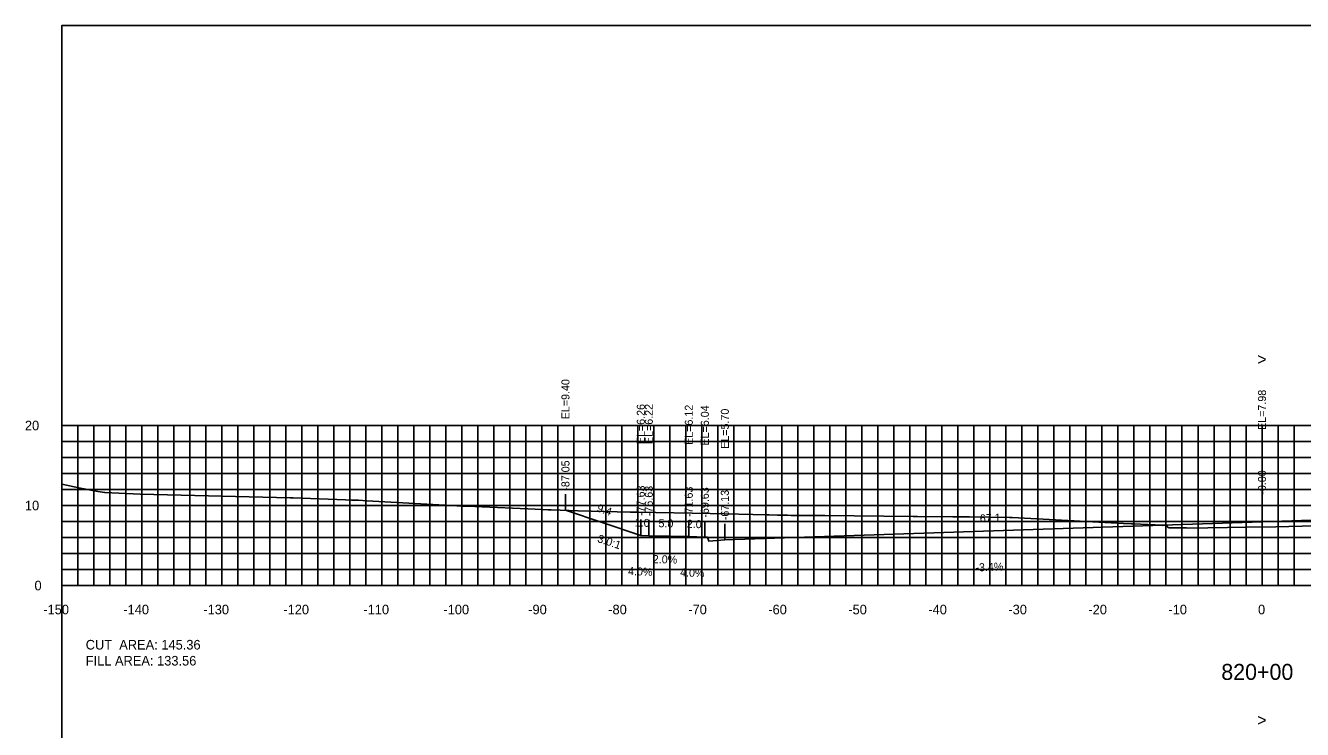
# Model space of a CAD drawing. Extents: x 1797419 to 1809236, y 248759 to 251512.
# Drawn here: x 1805876.5 to 1806036.1, y 250956.9 to 251044.9 of the extents above; entities that cross this region are included whole.
import ezdxf

# ---------------------------------------------------------------- set-up
doc = ezdxf.new("R2010")
doc.units = 0
for name, color, linetype in [('1', 7, 'Continuous'), ('10', 7, 'Continuous'), ('3', 7, 'Continuous'), ('31', 7, 'Continuous'), ('4', 7, 'Continuous'), ('60', 7, 'Continuous'), ('ANNO-TXT', 7, 'Continuous'), ('CL-CNST', 7, 'Continuous'), ('Level 62', 7, 'Continuous'), ('M-ROADS', 7, 'Continuous')]:
    doc.layers.add(name, color=color, linetype=linetype)

msp = doc.modelspace()

# ---------------------------------------------------------------- linework, layer by layer
for p, q in [((1805943.95, 250984.29), (1805943.95, 250986.29)), ((1806031, 250982.87), (1806031, 250984.87)), ((1805953.37, 250981.15), (1805953.37, 250983.15)), ((1805954.37, 250981.11), (1805954.37, 250983.11)), ((1805959.37, 250981.01), (1805959.37, 250983.01)), ((1805961.37, 250980.93), (1805961.37, 250982.93)), ((1805963.87, 250980.59), (1805963.87, 250982.59))]:
    msp.add_line(p, q)
msp.add_lwpolyline([(1805881, 250854.89), (1806181, 250854.89), (1806181, 251044.89), (1805881, 251044.89)], close=True)
at = {"layer": '60'}
for p, q in [((1805880.94, 250994.89), (1805881, 250994.89)), ((1805881, 250974.89), (1805881, 250994.89)), ((1805880.94, 250984.89), (1805881, 250984.89)), ((1805880.94, 250974.89), (1805881, 250974.89)), ((1805881, 250974.89), (1806181, 250974.89)), ((1805881, 250974.83), (1805881, 250974.89)), ((1805891, 250974.83), (1805891, 250974.89)), ((1805901, 250974.83), (1805901, 250974.89)), ((1805911, 250974.83), (1805911, 250974.89)), ((1805921, 250974.83), (1805921, 250974.89)), ((1805931, 250974.83), (1805931, 250974.89)), ((1805941, 250974.83), (1805941, 250974.89)), ((1805951, 250974.83), (1805951, 250974.89)), ((1805961, 250974.83), (1805961, 250974.89)), ((1805971, 250974.83), (1805971, 250974.89)), ((1805981, 250974.83), (1805981, 250974.89)), ((1805991, 250974.83), (1805991, 250974.89)), ((1806001, 250974.83), (1806001, 250974.89)), ((1806011, 250974.83), (1806011, 250974.89)), ((1806021, 250974.83), (1806021, 250974.89)), ((1806031, 250974.83), (1806031, 250974.89))]:
    msp.add_line(p, q, dxfattribs=at)
at = {"layer": 'CL-CNST'}
msp.add_lwpolyline([(1805943.95, 250984.29), (1805953.37, 250981.15), (1805954.37, 250981.11), (1805959.37, 250981.01), (1805961.37, 250980.93), (1805961.7, 250980.93), (1805961.87, 250980.43), (1805963.87, 250980.59), (1806031, 250982.87), (1806097.41, 250985.12), (1806099.41, 250984.96), (1806099.57, 250985.46), (1806099.9, 250985.46), (1806101.9, 250985.54), (1806106.9, 250985.64), (1806107.9, 250985.68), (1806114.23, 250983.57)], dxfattribs=at)
at = {"layer": 'Level 62'}
for p, q in [((1805881, 250994.89), (1806181, 250994.89)), ((1805881, 250974.89), (1805881, 250994.89)), ((1805883, 250974.89), (1805883, 250994.89)), ((1805885, 250974.89), (1805885, 250994.89)), ((1805887, 250974.89), (1805887, 250994.89)), ((1805889, 250974.89), (1805889, 250994.89)), ((1805891, 250974.89), (1805891, 250994.89)), ((1805893, 250974.89), (1805893, 250994.89)), ((1805895, 250974.89), (1805895, 250994.89)), ((1805897, 250974.89), (1805897, 250994.89)), ((1805899, 250974.89), (1805899, 250994.89)), ((1805901, 250974.89), (1805901, 250994.89)), ((1805903, 250974.89), (1805903, 250994.89)), ((1805905, 250974.89), (1805905, 250994.89)), ((1805907, 250974.89), (1805907, 250994.89)), ((1805909, 250974.89), (1805909, 250994.89)), ((1805911, 250974.89), (1805911, 250994.89)), ((1805913, 250974.89), (1805913, 250994.89)), ((1805915, 250974.89), (1805915, 250994.89)), ((1805917, 250974.89), (1805917, 250994.89)), ((1805919, 250974.89), (1805919, 250994.89)), ((1805921, 250974.89), (1805921, 250994.89)), ((1805923, 250974.89), (1805923, 250994.89)), ((1805925, 250974.89), (1805925, 250994.89)), ((1805927, 250974.89), (1805927, 250994.89)), ((1805929, 250974.89), (1805929, 250994.89)), ((1805931, 250974.89), (1805931, 250994.89)), ((1805933, 250974.89), (1805933, 250994.89)), ((1805935, 250974.89), (1805935, 250994.89)), ((1805937, 250974.89), (1805937, 250994.89)), ((1805939, 250974.89), (1805939, 250994.89)), ((1805941, 250974.89), (1805941, 250994.89)), ((1805943, 250974.89), (1805943, 250994.89)), ((1805945, 250974.89), (1805945, 250994.89)), ((1805947, 250974.89), (1805947, 250994.89)), ((1805949, 250974.89), (1805949, 250994.89)), ((1805951, 250974.89), (1805951, 250994.89)), ((1805953, 250974.89), (1805953, 250994.89)), ((1805955, 250974.89), (1805955, 250994.89)), ((1805957, 250974.89), (1805957, 250994.89)), ((1805959, 250974.89), (1805959, 250994.89)), ((1805961, 250974.89), (1805961, 250994.89)), ((1805963, 250974.89), (1805963, 250994.89)), ((1805965, 250974.89), (1805965, 250994.89)), ((1805967, 250974.89), (1805967, 250994.89)), ((1805969, 250974.89), (1805969, 250994.89)), ((1805971, 250974.89), (1805971, 250994.89)), ((1805973, 250974.89), (1805973, 250994.89)), ((1805975, 250974.89), (1805975, 250994.89)), ((1805977, 250974.89), (1805977, 250994.89)), ((1805979, 250974.89), (1805979, 250994.89)), ((1805981, 250974.89), (1805981, 250994.89)), ((1805983, 250974.89), (1805983, 250994.89)), ((1805985, 250974.89), (1805985, 250994.89)), ((1805987, 250974.89), (1805987, 250994.89)), ((1805989, 250974.89), (1805989, 250994.89)), ((1805991, 250974.89), (1805991, 250994.89)), ((1805993, 250974.89), (1805993, 250994.89)), ((1805995, 250974.89), (1805995, 250994.89)), ((1805997, 250974.89), (1805997, 250994.89)), ((1805999, 250974.89), (1805999, 250994.89)), ((1806001, 250974.89), (1806001, 250994.89)), ((1806003, 250974.89), (1806003, 250994.89)), ((1806005, 250974.89), (1806005, 250994.89)), ((1806007, 250974.89), (1806007, 250994.89)), ((1806009, 250974.89), (1806009, 250994.89)), ((1806011, 250974.89), (1806011, 250994.89)), ((1806013, 250974.89), (1806013, 250994.89)), ((1806015, 250974.89), (1806015, 250994.89)), ((1806017, 250974.89), (1806017, 250994.89)), ((1806019, 250974.89), (1806019, 250994.89)), ((1806021, 250974.89), (1806021, 250994.89)), ((1806023, 250974.89), (1806023, 250994.89)), ((1806025, 250974.89), (1806025, 250994.89)), ((1806027, 250974.89), (1806027, 250994.89)), ((1806029, 250974.89), (1806029, 250994.89)), ((1806031, 250974.89), (1806031, 250994.89)), ((1806033, 250974.89), (1806033, 250994.89)), ((1806035, 250974.89), (1806035, 250994.89)), ((1805881, 250992.89), (1806181, 250992.89)), ((1805881, 250990.89), (1806181, 250990.89)), ((1805881, 250988.89), (1806181, 250988.89)), ((1805881, 250986.89), (1806181, 250986.89)), ((1805881, 250984.89), (1806181, 250984.89)), ((1805881, 250982.89), (1806181, 250982.89)), ((1805881, 250980.89), (1806181, 250980.89)), ((1805881, 250978.89), (1806181, 250978.89)), ((1805881, 250976.89), (1806181, 250976.89)), ((1805881, 250974.89), (1806181, 250974.89))]:
    msp.add_line(p, q, dxfattribs=at)
at = {"layer": 'M-ROADS'}
msp.add_lwpolyline([(1805881, 250987.58), (1805883.15, 250987.1), (1805885.53, 250986.66), (1805886.38, 250986.51), (1805890.82, 250986.29), (1805909.56, 250985.87), (1805909.7, 250985.86), (1805909.93, 250985.87), (1805916.46, 250985.61), (1805917.21, 250985.57), (1805917.23, 250985.57), (1805917.51, 250985.56), (1805917.52, 250985.56), (1805918.07, 250985.56), (1805919.15, 250985.49), (1805931.11, 250984.8), (1805931.44, 250984.8), (1805931.67, 250984.8), (1805941.13, 250984.39), (1805941.78, 250984.36), (1805942.16, 250984.35), (1805945.56, 250984.23), (1805952.04, 250984.06), (1805952.6, 250984.06), (1805952.99, 250984.06), (1805962.05, 250983.9), (1805969.16, 250983.73), (1805969.42, 250983.73), (1805970.44, 250983.7), (1805971.69, 250983.67), (1805972.15, 250983.66), (1805972.69, 250983.66), (1805972.73, 250983.66), (1805976.36, 250983.63), (1805987.41, 250983.53), (1805987.84, 250983.53), (1805987.95, 250983.53), (1805992.35, 250983.47), (1805992.69, 250983.47), (1805993.29, 250983.46), (1805993.99, 250983.49), (1805994.43, 250983.48), (1805999.45, 250983.38), (1805999.78, 250983.39), (1806013.67, 250982.65), (1806014.69, 250982.59), (1806014.91, 250982.59), (1806018.56, 250982.42), (1806018.56, 250982.42), (1806018.66, 250982.41), (1806019.03, 250982.42), (1806019.33, 250982.12), (1806021.58, 250982.1), (1806021.82, 250982.06), (1806029.11, 250982.19), (1806032.73, 250982.24), (1806040.93, 250982.43)], dxfattribs=at)

# ---------------------------------------------------------------- texts
msp.add_text('3.0:1', height=1, rotation=341.5651).set_placement((1805947.87, 250980.35))
at = {"layer": '1'}
msp.add_text('820+00', height=2, dxfattribs=at).set_placement((1806025.91, 250963.09))
at = {"layer": '10'}
for s, p in [('-150', (1805878.7, 250971.29)), ('-140', (1805888.7, 250971.29)), ('-130', (1805898.7, 250971.29)), ('-120', (1805908.7, 250971.29)), ('-110', (1805918.7, 250971.29)), ('-100', (1805928.7, 250971.29)), ('-90', (1805939.3, 250971.29)), ('-80', (1805949.3, 250971.29)), ('-70', (1805959.3, 250971.29)), ('-60', (1805969.3, 250971.29)), ('-50', (1805979.3, 250971.29)), ('-40', (1805989.3, 250971.29)), ('-30', (1805999.3, 250971.29)), ('-20', (1806009.3, 250971.29)), ('-10', (1806019.3, 250971.29)), ('0', (1806030.5, 250971.29))]:
    msp.add_text(s, height=1.2, dxfattribs=at).set_placement(p)
at = {"layer": '3'}
for s, p in [('EL=9.40', (1805944.45, 250995.67)), ('EL=7.98', (1806031.5, 250994.34)), ('EL=6.26', (1805953.87, 250992.56)), ('EL=6.22', (1805954.87, 250992.57)), ('EL=6.12', (1805959.87, 250992.47)), ('EL=6.04', (1805961.87, 250992.39)), ('EL=5.70', (1805964.37, 250991.98)), ('-87.05', (1805944.45, 250986.74)), ('-0.00', (1806031.5, 250986.24)), ('-77.63', (1805953.87, 250983.6)), ('-76.63', (1805954.87, 250983.56)), ('-71.63', (1805959.87, 250983.46)), ('-69.63', (1805961.87, 250983.38)), ('-67.13', (1805964.37, 250983.05))]:
    msp.add_text(s, height=1, rotation=90, dxfattribs=at).set_placement(p)
at = {"layer": '31'}
for s, p in [('20', (1805876.4, 250994.29)), ('10', (1805876.4, 250984.29)), ('0', (1805877.6, 250974.29))]:
    msp.add_text(s, height=1.2, dxfattribs=at).set_placement(p)
at = {"layer": '4'}
for s, rotation, p in [('9.4', 341.5651, (1805947.79, 250984.17)), ('1.0', 357.7094, (1805952.6, 250982.28)), ('5.0', 358.8542, (1805955.57, 250982.18)), ('2.0', 357.7094, (1805959.1, 250982.12)), ('67.1', 1.9432, (1805995.75, 250982.78)), ('2.0%', 358.8542, (1805954.86, 250977.69)), ('4.0%', 357.7094, (1805951.76, 250976.21)), ('4.0%', 357.7094, (1805958.26, 250976.05)), ('-3.4%', 1.9432, (1805995.2, 250976.65))]:
    msp.add_text(s, height=1, rotation=rotation, dxfattribs=at).set_placement(p)
at = {"layer": '60'}
for s, height, p in [('>', 1.5, (1806030.39, 251002.43)), ('-', 0.0001, (1805881, 250974.89)), ('>', 1.5, (1806030.39, 250957.33))]:
    msp.add_text(s, height=height, dxfattribs=at).set_placement(p)
at = {"layer": 'ANNO-TXT'}
for s, p in [('CUT  AREA: 145.36', (1805884, 250966.89)), ('FILL AREA: 133.56', (1805884, 250964.89))]:
    msp.add_text(s, height=1.2, dxfattribs=at).set_placement(p)

doc.saveas('drawing.dxf')
